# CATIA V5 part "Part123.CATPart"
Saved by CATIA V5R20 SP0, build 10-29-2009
Part number: FA 084700-2 comprimido
Revision: ANY
Definition: UNKNOWN
Nomenclature: FA 084700-2 comprimido
Source: Unknown
Bounding box of the stored display mesh (mm): x -2.45 to 2.45, y 0 to 4.72, z -2.45 to 2.45
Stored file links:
  C:\Users\Utente\Desktop\IO LAVORO\3D X SITO CF\CUMSA\3D files FA\FA 084705-20\Part123.CATPart

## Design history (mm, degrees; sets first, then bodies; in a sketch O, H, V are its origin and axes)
Body1 "Cortar-Extruir1" (main body)
  Solid1: solid without history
